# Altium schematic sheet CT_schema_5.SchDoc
size 578 x 363 mm
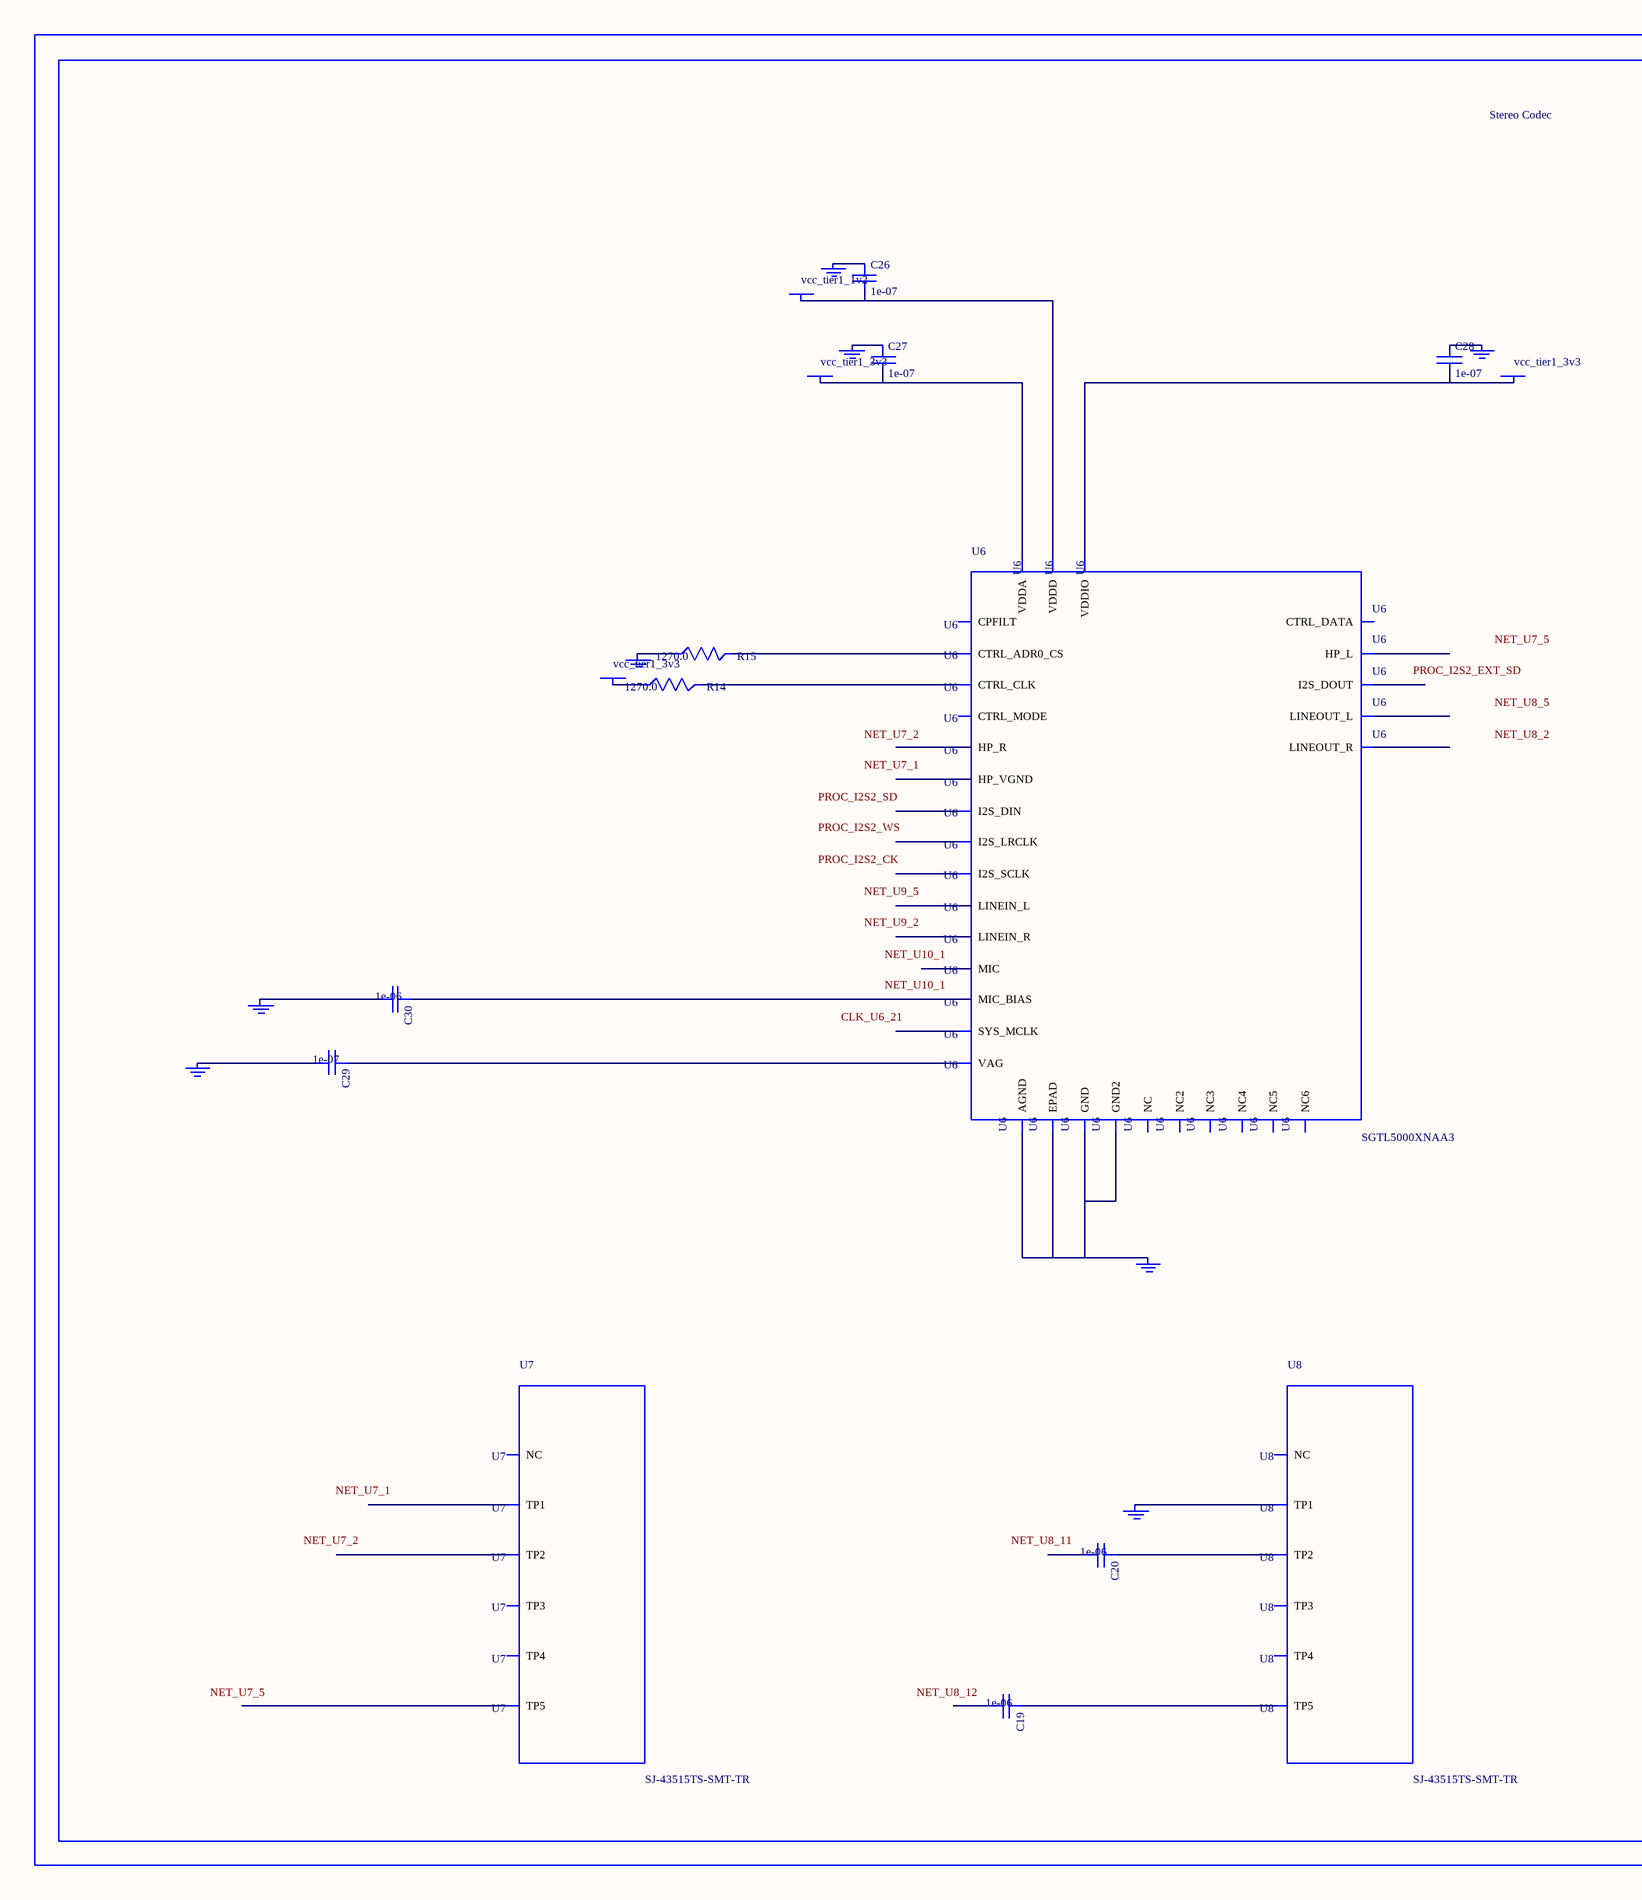
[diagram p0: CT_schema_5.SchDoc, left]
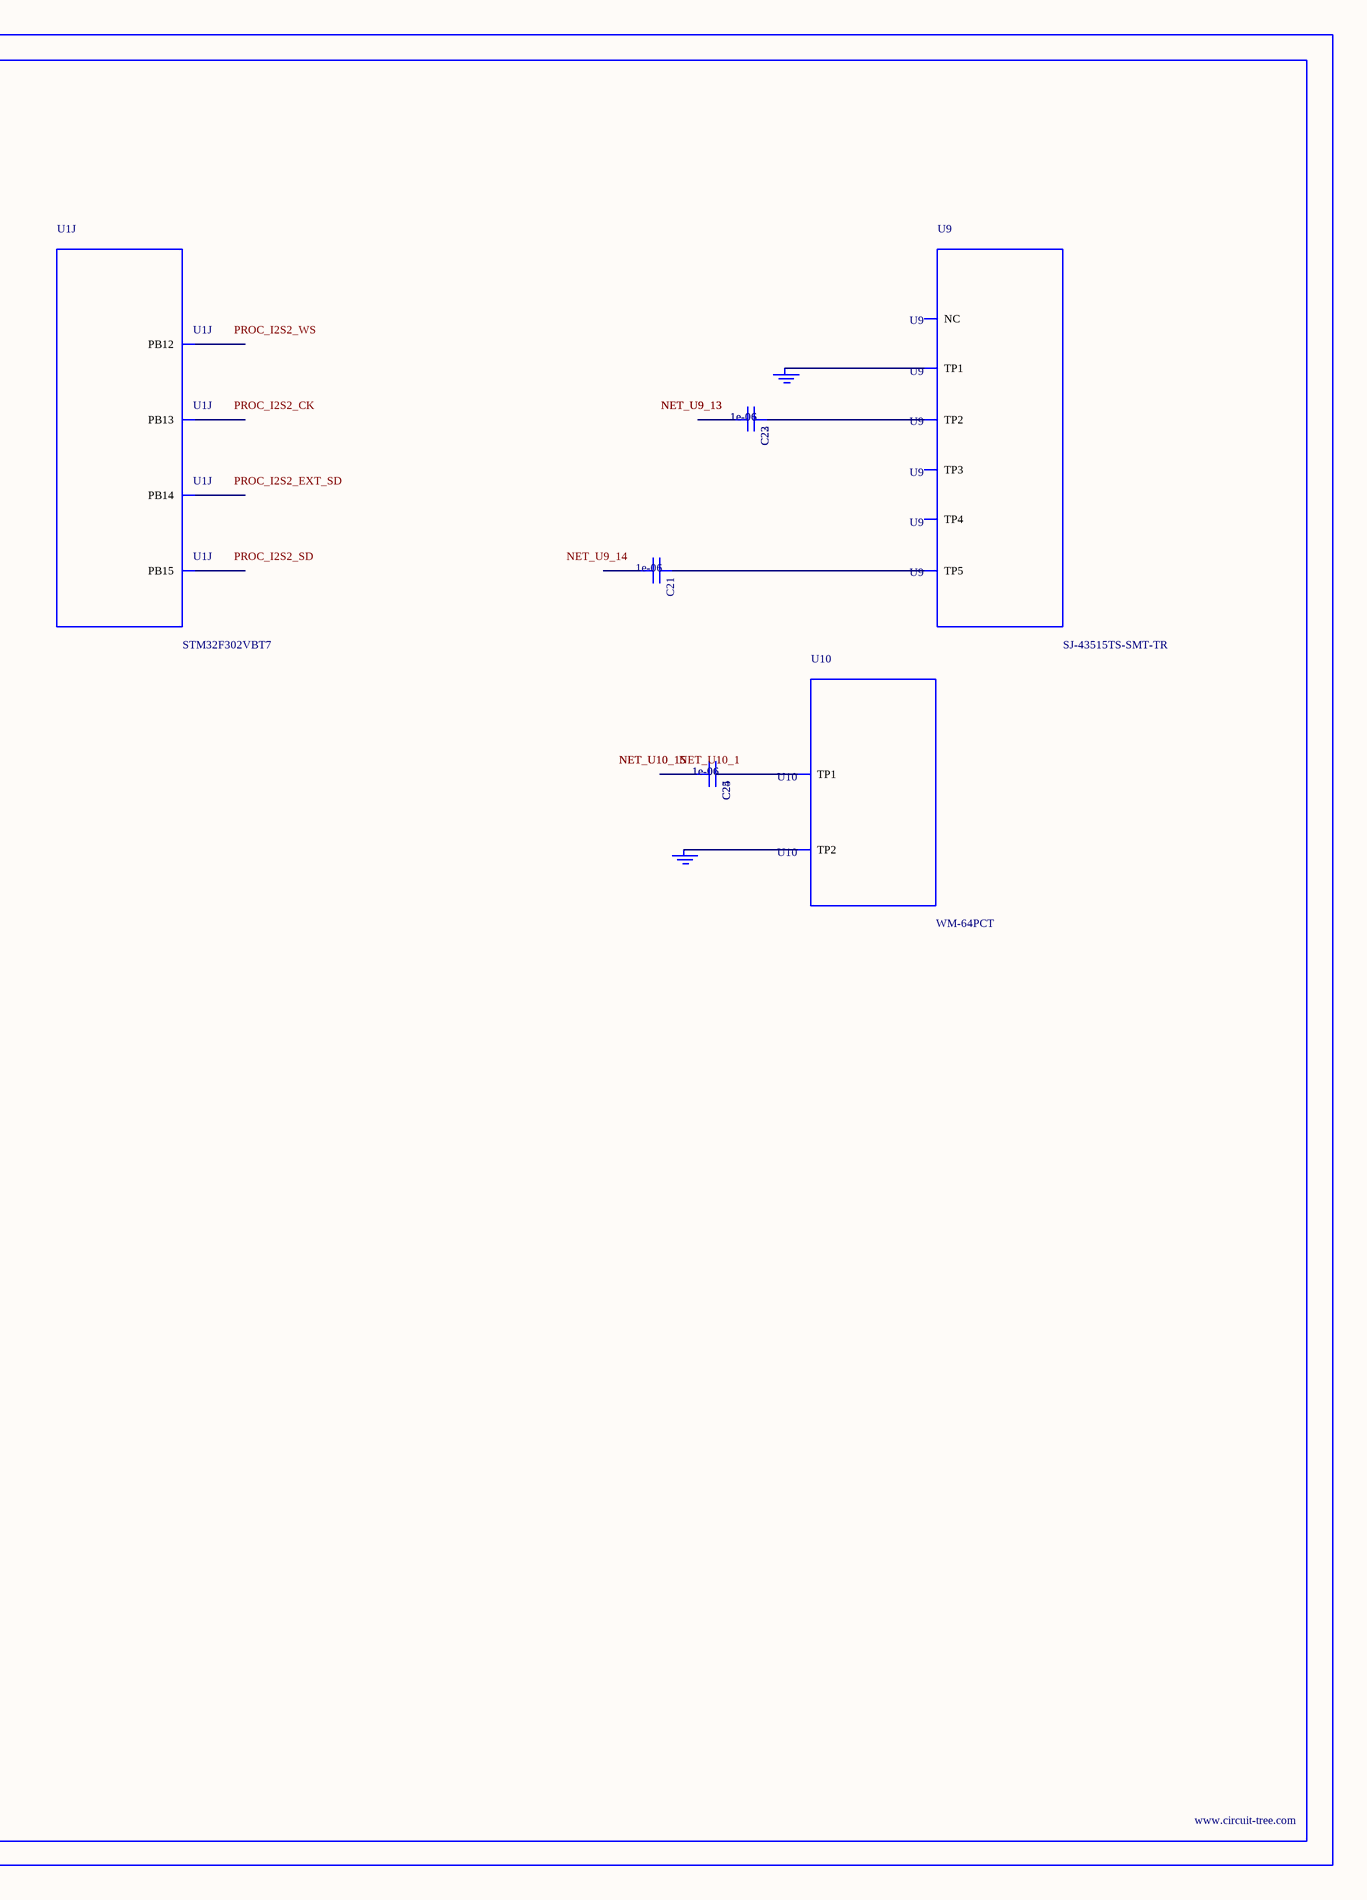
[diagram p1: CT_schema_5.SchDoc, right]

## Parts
BORDER4  (no value)
C19  1e-06  [C0603]
C20  1e-06  [C0603]
C21  1e-06  [C0603]
C22  1e-06  [C0603]
C23  1e-06  [C0603]
C24  1e-06  [C0603]
C25  1e-06  [C0603]
C26  1e-07  [C0402]
C27  1e-07  [C0402]
C28  1e-07  [C0402]
C29  1e-07  [C0402]
C30  1e-06  [C0603]
GND_INSTANCE_4_0  (no value)
GND_INSTANCE_4_1  (no value)
GND_INSTANCE_4_2  (no value)
GND_INSTANCE_4_3  (no value)
GND_INSTANCE_4_4  (no value)
GND_INSTANCE_4_5  (no value)
GND_INSTANCE_4_6  (no value)
GND_INSTANCE_4_7  (no value)
GND_INSTANCE_4_8  (no value)
GND_INSTANCE_4_9  (no value)
GND_INSTANCE_4_10  (no value)
POWER_INSTANCE_4_0  vcc_tier1_3v3
POWER_INSTANCE_4_1  vcc_tier1_3v3
POWER_INSTANCE_4_2  vcc_tier1_3v3
POWER_INSTANCE_4_3  vcc_tier1_1v2
R14  1270.0  [R0603]
R15  1270.0  [R0603]
U1  STM32F302VBT7  [LQFP100]  (part J of 11)
U6  SGTL5000XNAA3  [QFN-32]
U7  SJ-43515TS-SMT-TR  [SJ-43515TS-SMT-TR]
U8  SJ-43515TS-SMT-TR  [SJ-43515TS-SMT-TR]
U9  SJ-43515TS-SMT-TR  [SJ-43515TS-SMT-TR]
U10  WM-64PCT  [WM-64PC]

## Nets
NetC19_1: C19.1 U8.5(TP5)
NetC20_1: C20.1 U8.2(TP2)
NetC21_1: C21.1 U9.5(TP5)
NetC22_1: C22.1 C23.1 U9.2(TP2)
NetC22_2: C22.2 C23.2
NetC24_1: C24.1 C25.1 U10.1(TP1)
NetC24_2: C24.2 C25.2
NetC26_1: C26.1 GND_INSTANCE_4_5.0(GND)
NetC26_2: C26.2 POWER_INSTANCE_4_3.0(PWR) U6.30(VDDD)
NetC27_1: C27.1 GND_INSTANCE_4_1.0(GND)
NetC27_2: C27.2 POWER_INSTANCE_4_0.0(PWR) U6.5(VDDA)
NetC28_1: C28.1 GND_INSTANCE_4_4.0(GND)
NetC28_2: C28.2 POWER_INSTANCE_4_1.0(PWR) U6.20(VDDIO)
NetC29_1: C29.1 U6.10(VAG)
NetC29_2: C29.2 GND_INSTANCE_4_2.0(GND)
NetC30_1: C30.1 U6.16(MIC_BIAS)
NetC30_2: C30.2 GND_INSTANCE_4_3.0(GND)
NetGND_INSTANCE_4_0_0: GND_INSTANCE_4_0.0(GND) U6.1(GND) U6.3(GND2) U6.7(AGND) U6.EXP(EPAD)
NetGND_INSTANCE_4_6_0: GND_INSTANCE_4_6.0(GND) R15.1
NetGND_INSTANCE_4_7_0: GND_INSTANCE_4_7.0(GND) U8.1(TP1)
NetGND_INSTANCE_4_8_0: GND_INSTANCE_4_8.0(GND) GND_INSTANCE_4_9.0(GND) U9.1(TP1)
NetGND_INSTANCE_4_10_0: GND_INSTANCE_4_10.0(GND) U10.2(TP2)
NetPOWER_INSTANCE_4_2_0: POWER_INSTANCE_4_2.0(PWR) R14.1
NetR14_2: R14.2 U6.29(CTRL_CLK)
NetR15_2: R15.2 U6.31(CTRL_ADR0_CS)

Not connected (* = marked no-connect by the designer): C19 2; C20 2; C21 2; U1 51(PB12) 52(PB13) 53(PB14) 54(PB15); U6 2(HP_R) 4(HP_VGND) 6(HP_L) 8(NC) 9(NC2) 11(LINEOUT_R) 12(LINEOUT_L) 13(LINEIN_R) 14(LINEIN_L) 15(MIC) 17(NC3) 18(CPFILT) 19(NC4) 21(SYS_MCLK) 22(NC5) 23(I2S_LRCLK) 24(I2S_SCLK) 25(I2S_DOUT) 26(I2S_DIN) 27(CTRL_DATA) 28(NC6) 32(CTRL_MODE); U7 1(TP1) 2(TP2) 3(TP3) 4(TP4) 5(TP5) 6(NC); U8 3(TP3) 4(TP4) 6(NC); U9 3(TP3) 4(TP4) 6(NC)

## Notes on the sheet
- Labels drawn without touching a wire or pin: CLK_U6_21, NET_U7_1, NET_U7_2, NET_U7_5, NET_U8_2, NET_U8_5, NET_U8_11, NET_U8_12, NET_U9_2, NET_U9_5, NET_U9_14, NET_U10_1, PROC_I2S2_CK, PROC_I2S2_EXT_SD, PROC_I2S2_SD, PROC_I2S2_WS

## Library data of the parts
BORDER4 = BORDER_PAGE4
C19-C25 C30 = C0603C105K3RACTU
C26-C29 = C0402C104K3RACTU
GND_INSTANCE_4_0-GND_INSTANCE_4_10 = GND
POWER_INSTANCE_4_0-POWER_INSTANCE_4_3 = PWR
R14 R15 = RC0603FR-071K27L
